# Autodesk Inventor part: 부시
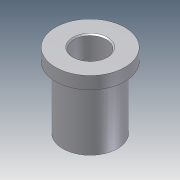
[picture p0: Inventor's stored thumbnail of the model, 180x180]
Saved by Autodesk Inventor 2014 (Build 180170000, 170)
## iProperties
Company: 한국ATC센터
Created: 2014-01
Part Number: 부시
Document SubType Name: Modeling
Designer: KYOUNG IL JANG
Density: 1 g/cm^3
Material: 강철
Mass: 8.58964 g
Surface Area: 43.3569 cm^2
Volume: 8.58964 cm^3
Vendor: CBT Solutions
Appearance: 강철
Author: KYOUNG IL JANG
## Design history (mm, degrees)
sketch "스케치1"
  geometry: C1 r 11 at (0, 0) reference; C2 r 14 at (0, 0) reference; C3 r 11 at (0, 0) reference; 1 further point
  node "참조1"
  node "참조2"
extrude "돌출1" new body sketch "스케치1" distance "d0" = 5; taper "d1" = 0 deg
extrude "돌출2" join sketch "스케치1" distance "d2" = 25; taper "d3" = 0 deg
hole "구멍1" diameter "d6" = 13; stored, may be unused: countersink angle "d10" = 90 deg, drill point angle "d12" = 118 deg; dims "d4" = 10, "d5" = 10, "d7" = 6, "d8" = 4, "d9" = 2, "d11" = 8
chamfer "모따기1" distance "d13" = 0.5; stored, may be unused: second distance "d14" = 2, angle "d15" = 45 deg
node "솔리드1"
